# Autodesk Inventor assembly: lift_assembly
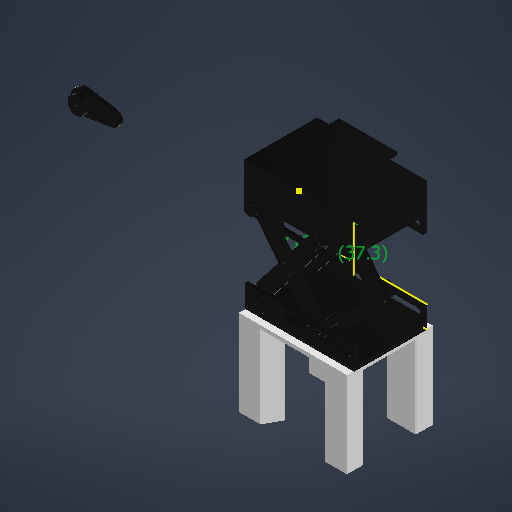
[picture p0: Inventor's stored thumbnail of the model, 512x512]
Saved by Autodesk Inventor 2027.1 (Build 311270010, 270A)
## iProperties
Created: 2026-11
Part Number: lift_assembly
Document SubType Name: Assembly
Designer: djshs
Author: djshs
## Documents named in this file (15)
- C:\Users\djshs\OneDrive\Desktop\ROKEY BOOT CAMP\project1\lift\lift_assembly.iam
- C:\Users\djshs\Downloads\초소형리프트_90x60\stl\01_하판_x1.ipt
- C:\Users\djshs\Downloads\초소형리프트_90x60\stl\06_푸시로드_x1.ipt
- C:\Users\djshs\Downloads\초소형리프트_90x60\stl\07_크랭크_스플라인5.9_x1.ipt
- C:\Users\djshs\Downloads\초소형리프트_90x60\stl\10_핀6_아래고정_x2.ipt
- C:\Users\djshs\Downloads\초소형리프트_90x60\stl\03_시저팔_바깥A_x2.ipt
- C:\Users\djshs\Downloads\초소형리프트_90x60\stl\14_클립6_x8.ipt
- C:\Users\djshs\Downloads\초소형리프트_90x60\stl\03_시저팔_안쪽B_x2.ipt
- C:\Users\djshs\Downloads\초소형리프트_90x60\stl\08_슬라이더축_x2.ipt
- C:\Users\djshs\Downloads\초소형리프트_90x60\stl\09_스페이서_x6.ipt
- C:\Users\djshs\Downloads\초소형리프트_90x60\stl\04_아래슬라이더바_x1.ipt
- C:\Users\djshs\Downloads\초소형리프트_90x60\stl\02_상판_x1.ipt
- C:\Users\djshs\Downloads\초소형리프트_90x60\stl\12_핀6_위고정_x2.ipt
- C:\Users\djshs\Downloads\초소형리프트_90x60\stl\05_위슬라이더바_x1.ipt
- C:\Users\djshs\Downloads\초소형리프트_90x60\stl\11_핀6_가운데_x2.ipt
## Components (28 placed, 14 different names)
1. 01_하판_x1:1
2. 06_푸시로드_x1:1
3. 07_크랭크_스플라인5.9_x1:1
4. 10_핀6_아래고정_x2:1
5. 10_핀6_아래고정_x2:2 — 강체:1
6. 14_클립6_x8:1
7. 08_슬라이더축_x2:1
8. 09_스페이서_x6:1
9. 03_시저팔_바깥A_x2:2
10. 03_시저팔_안쪽B_x2:2
11. 04_아래슬라이더바_x1:1 — 각도:3
12. 03_시저팔_안쪽B_x2:3
13. 09_스페이서_x6:2
14. 14_클립6_x8:2
15. 03_시저팔_바깥A_x2:3 — 강체:1
16. 02_상판_x1:1
17. 09_스페이서_x6:3
18. 08_슬라이더축_x2:3
19. 12_핀6_위고정_x2:1
20. 12_핀6_위고정_x2:2
21. 14_클립6_x8:3
22. 14_클립6_x8:4
23. 14_클립6_x8:5
24. 05_위슬라이더바_x1:1 — 각도:2
25. 09_스페이서_x6:4
26. 14_클립6_x8:6
27. 11_핀6_가운데_x2:1
28. 11_핀6_가운데_x2:2
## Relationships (3: Angle 2, WeldJoint 1)
- 강체:1 [WeldJoint]: 10_핀6_아래고정_x2:2 ↔ 03_시저팔_바깥A_x2:3
- 각도:2 [Angle]: 05_위슬라이더바_x1:1
- 각도:3 [Angle]: 04_아래슬라이더바_x1:1
